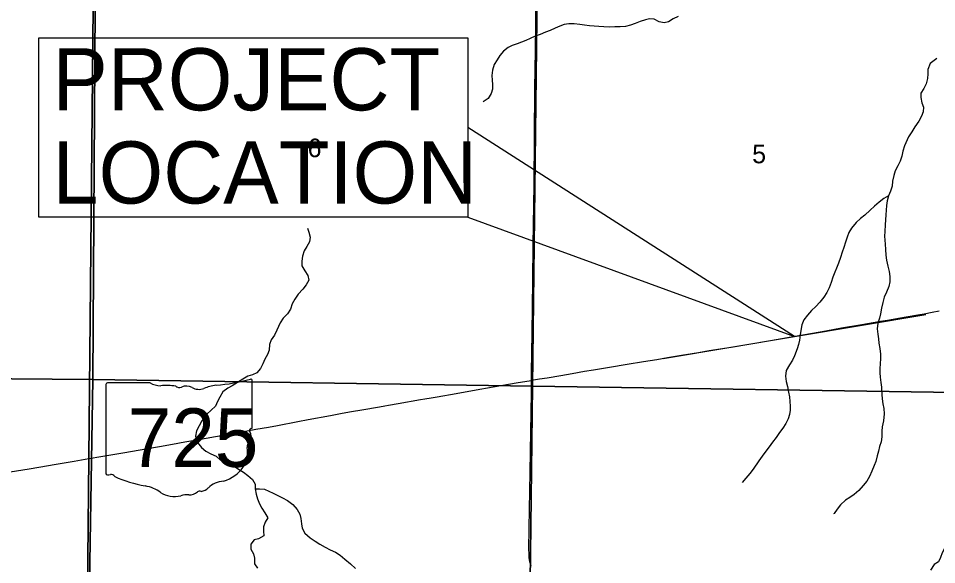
# Model space of a CAD drawing. Extents: x 0 to 34, y 0 to 22.
# Drawn here: x 3.317 to 5.385, y 16.874 to 18.105 of the extents above; entities that cross this region are included whole.
import ezdxf

# ---------------------------------------------------------------- set-up
doc = ezdxf.new("R2010")
doc.units = 0
for name, color, linetype in [('GM_X_Corporation', 7, 'Continuous'), ('GM_X_County_Road', 7, 'Continuous'), ('GM_X_Minor_River', 7, 'Continuous'), ('GM_X_Section_Text', 7, 'Continuous'), ('GM_X_State_Route', 7, 'Continuous'), ('GM_X_State_Shield', 7, 'Continuous'), ('SH_Data', 7, 'Continuous')]:
    doc.layers.add(name, color=color, linetype=linetype)

msp = doc.modelspace()

# ---------------------------------------------------------------- linework, layer by layer
at = {"layer": 'GM_X_Corporation'}
for points in [[(2.4847, 18.3876), (3.4912, 18.3726), (3.4847, 17.2912), (2.4791, 17.2994)], [(3.4912, 18.3726), (4.4615, 18.3587), (4.4872, 18.3578), (4.475, 17.2762), (3.4847, 17.2912)], [(4.4872, 18.3578), (5.4612, 18.3442), (5.4991, 18.3437), (5.4781, 17.2612), (4.475, 17.2762)], [(3.4847, 17.2912), (3.4681, 16.2816), (2.4544, 16.3158), (2.4791, 17.2994)], [(4.475, 17.2762), (4.463, 16.2688), (3.4681, 16.2816), (3.4847, 17.2912)], [(5.4781, 17.2612), (5.4651, 16.258), (4.463, 16.2688), (4.475, 17.2762)]]:
    msp.add_lwpolyline(points, close=True, dxfattribs=at)
for points in [[(3.4672, 16.2781), (3.4754, 17.1134), (3.4875, 18.3666), (3.4876, 18.3718), (3.4864, 18.3719), (3.3947, 18.3734), (3.3557, 18.374), (3.2311, 18.3758)], [(3.4875, 18.3666), (3.4754, 17.1134), (3.4672, 16.2781)]]:
    msp.add_lwpolyline(points, dxfattribs=at)
at = {"layer": 'GM_X_County_Road'}
for points in [[(4.4727, 17.2893), (4.4727, 17.2905), (4.4727, 17.3067), (4.474, 17.3955), (4.4755, 17.5136), (4.4765, 17.5944), (4.4782, 17.7292), (4.4793, 17.8391), (4.4802, 17.9473), (4.4812, 18.0329), (4.482, 18.0907), (4.4827, 18.1677), (4.4833, 18.2397), (4.4839, 18.3062), (4.4838, 18.3193), (4.4834, 18.3262), (4.4827, 18.3312), (4.4817, 18.3355), (4.4807, 18.3391), (4.4789, 18.3438), (4.4765, 18.3487), (4.4749, 18.3519), (4.4733, 18.3544), (4.4712, 18.3572)], [(4.4714, 16.8701), (4.469, 16.8803), (4.4675, 16.89), (4.4669, 16.8986), (4.4667, 16.9079), (4.4675, 16.9557), (4.4692, 17.0825), (4.47, 17.129), (4.4721, 17.2607), (4.4727, 17.2893)]]:
    msp.add_lwpolyline(points, dxfattribs=at)
at = {"layer": 'GM_X_Minor_River'}
for points in [[(4.8026, 18.1094), (4.7915, 18.1043), (4.7811, 18.0973), (4.7712, 18.0949), (4.7603, 18.0973), (4.7486, 18.1036), (4.7384, 18.1038), (4.7289, 18.1017), (4.7174, 18.0978), (4.7056, 18.0934), (4.6956, 18.0898), (4.6842, 18.087), (4.6724, 18.0857), (4.6603, 18.0859), (4.6481, 18.0854), (4.6356, 18.0856), (4.6239, 18.0866), (4.6136, 18.0875), (4.603, 18.0881), (4.592, 18.0895), (4.5814, 18.0912), (4.5682, 18.0929), (4.5568, 18.0924), (4.5462, 18.0911), (4.5362, 18.0875), (4.5259, 18.0827), (4.5148, 18.078), (4.5037, 18.0736), (4.4919, 18.0689), (4.4808, 18.065), (4.4697, 18.0599)], [(4.4697, 18.0599), (4.4594, 18.0551), (4.4498, 18.0515), (4.4399, 18.0479), (4.4292, 18.0439), (4.4196, 18.0392), (4.4096, 18.0314), (4.4011, 18.0213), (4.3948, 18.0116), (4.3885, 18.0011), (4.3849, 17.9886), (4.3832, 17.9762), (4.3837, 17.9655), (4.3847, 17.9556), (4.3849, 17.9458), (4.3813, 17.936), (4.3746, 17.9247), (4.3638, 17.9166)], [(5.3856, 18.0144), (5.3702, 18.0033), (5.365, 17.9898), (5.3648, 17.9799), (5.3643, 17.9697), (5.3614, 17.9576), (5.3563, 17.9467), (5.3492, 17.9362), (5.3494, 17.9267), (5.3519, 17.9149), (5.3551, 17.905), (5.3545, 17.8944), (5.351, 17.8846), (5.3447, 17.873), (5.3361, 17.8606), (5.3287, 17.849), (5.3213, 17.8378), (5.3125, 17.8174), (5.3089, 17.8054), (5.3064, 17.7944), (5.3028, 17.7835), (5.2977, 17.7726), (5.2914, 17.761), (5.2882, 17.7508), (5.2856, 17.7379), (5.2851, 17.727), (5.2807, 17.7157), (5.2763, 17.7047), (5.2734, 17.6934), (5.2721, 17.6832), (5.2712, 17.673), (5.2702, 17.662), (5.2696, 17.651), (5.269, 17.6393), (5.268, 17.6245), (5.2678, 17.6143), (5.269, 17.5961), (5.2695, 17.5839), (5.2704, 17.571), (5.2721, 17.5603), (5.2749, 17.5463), (5.2781, 17.5345), (5.2794, 17.5234), (5.2792, 17.5113), (5.2771, 17.5007), (5.2719, 17.4879), (5.2664, 17.4767), (5.2635, 17.4646), (5.261, 17.4521), (5.2585, 17.4393), (5.2564, 17.4291), (5.2528, 17.4178), (5.2507, 17.4053), (5.2524, 17.3935), (5.2541, 17.3825), (5.255, 17.373), (5.2567, 17.3608), (5.2584, 17.3483), (5.2585, 17.3373), (5.258, 17.3274)], [(5.2763, 17.7047), (5.2663, 17.6992), (5.2552, 17.6911), (5.2451, 17.6818), (5.2355, 17.6729), (5.2235, 17.6617), (5.2135, 17.6536), (5.2039, 17.645), (5.193, 17.6324), (5.1875, 17.6226), (5.1835, 17.6117), (5.1799, 17.6007), (5.1755, 17.5883), (5.1723, 17.5778), (5.1683, 17.5657), (5.1642, 17.5533), (5.1511, 17.5217), (5.1471, 17.5096), (5.1427, 17.4975), (5.1376, 17.4874), (5.1306, 17.4765), (5.1216, 17.4653), (5.1127, 17.4556), (5.1027, 17.4467), (5.0938, 17.4363), (5.086, 17.4254), (5.0812, 17.4141), (5.0791, 17.4017), (5.0778, 17.3914), (5.076, 17.3797), (5.074, 17.3699), (5.0708, 17.3601), (5.0644, 17.3447), (5.06, 17.3345), (5.0534, 17.3237), (5.0463, 17.3113), (5.0442, 17.2984), (5.0459, 17.2863), (5.0491, 17.2752), (5.0515, 17.2623), (5.0536, 17.2516), (5.0545, 17.2413), (5.0551, 17.2311), (5.0553, 17.2216), (5.0536, 17.2118), (5.0508, 17.202), (5.0453, 17.1919), (5.0382, 17.181), (5.0312, 17.1713), (5.0238, 17.16), (5.0153, 17.1496), (5.0075, 17.1391), (5.0001, 17.1294), (4.9919, 17.1185), (4.9841, 17.1077), (4.9713, 17.089), (4.9639, 17.0789), (4.9553, 17.0684), (4.9468, 17.0587)], [(3.9679, 17.6324), (3.9707, 17.6232), (3.9735, 17.6118), (3.9722, 17.6015), (3.9667, 17.591), (3.9604, 17.5809), (3.9564, 17.5692), (3.955, 17.5579), (3.9548, 17.5469), (3.9622, 17.5361), (3.9689, 17.5254), (3.9706, 17.5151), (3.9651, 17.5046), (3.9573, 17.4949), (3.9472, 17.483), (3.939, 17.4721), (3.9335, 17.4616), (3.9295, 17.4495), (3.9225, 17.4394), (3.9128, 17.429), (3.9066, 17.4185), (3.8991, 17.4023), (3.8939, 17.3907), (3.8861, 17.3806), (3.8825, 17.37), (3.8819, 17.3575), (3.8775, 17.347), (3.872, 17.3365), (3.8673, 17.3263), (3.8618, 17.3158), (3.8537, 17.3061), (3.8441, 17.3013), (3.8334, 17.2985)], [(5.258, 17.3274), (5.2566, 17.3153), (5.2568, 17.3058), (5.2578, 17.2959), (5.2591, 17.2842), (5.2604, 17.2739), (5.2616, 17.2572), (5.2622, 17.2477), (5.2635, 17.2363), (5.2656, 17.2257), (5.2669, 17.2139), (5.2655, 17.1976), (5.2625, 17.184), (5.2616, 17.1742), (5.2614, 17.162), (5.2597, 17.1503), (5.256, 17.1398), (5.2536, 17.1292), (5.2507, 17.119), (5.2478, 17.1065), (5.2442, 17.0968), (5.2391, 17.0847), (5.2336, 17.0723), (5.2273, 17.0618), (5.2191, 17.0517), (5.2094, 17.0405), (5.1994, 17.032), (5.1891, 17.0254), (5.1794, 17.0191), (5.1683, 17.0087), (5.1605, 16.999), (5.1539, 16.9892), (5.1523, 16.9881)], [(3.8334, 17.2985), (3.8219, 17.2919), (3.8104, 17.2845), (3.7985, 17.2768), (3.7885, 17.2717), (3.7774, 17.2635), (3.7703, 17.2515), (3.7652, 17.2414), (3.7608, 17.2308), (3.7512, 17.2219), (3.7408, 17.2126), (3.7295, 17.1981), (3.7236, 17.1868), (3.7181, 17.1751), (3.7159, 17.1634), (3.7199, 17.1493), (3.7291, 17.1378), (3.7392, 17.1296), (3.7505, 17.1234), (3.7618, 17.1182), (3.7715, 17.1101), (3.7813, 17.1046), (3.7918, 17.101), (3.8027, 17.0955), (3.8125, 17.0888), (3.8237, 17.0818), (3.8335, 17.0748), (3.8439, 17.0655), (3.8498, 17.0552), (3.85, 17.0445), (3.8524, 17.0328), (3.8556, 17.0221), (3.86, 17.011), (3.8647, 17.0011), (3.8717, 16.9907), (3.8784, 16.9792), (3.8725, 16.9691), (3.8685, 16.9589), (3.8691, 16.949), (3.8693, 16.9388), (3.8578, 16.9322), (3.8475, 16.9297), (3.8401, 16.92), (3.8403, 16.9082), (3.8461, 16.8979), (3.8482, 16.8884), (3.8488, 16.8755), (3.855, 16.8655)], [(3.85, 17.0445), (3.8595, 17.0444), (3.8708, 17.0438), (3.881, 17.0394), (3.8908, 17.0351), (3.9013, 17.0296), (3.9115, 17.0245), (3.9231, 17.0182), (3.9347, 17.0092), (3.9447, 16.9981), (3.9506, 16.9873), (3.9531, 16.9778), (3.9544, 16.966), (3.9557, 16.9561), (3.9616, 16.945), (3.9739, 16.9342), (3.9855, 16.9264), (3.9957, 16.9201), (4.0077, 16.9127), (4.0186, 16.9072), (4.031, 16.9021), (4.0411, 16.8954), (4.0519, 16.8857), (4.065, 16.8753), (4.0758, 16.8648)], [(5.5021, 16.9619), (5.492, 16.9507), (5.4815, 16.9384), (5.4737, 16.9283), (5.4664, 16.9186), (5.4567, 16.9108), (5.4467, 16.9045), (5.4368, 16.9002), (5.424, 16.9068), (5.4131, 16.9139), (5.4028, 16.9099), (5.397, 16.9001), (5.3937, 16.89), (5.389, 16.8802), (5.379, 16.8739), (5.3708, 16.8616)]]:
    msp.add_lwpolyline(points, dxfattribs=at)
at = {"layer": 'GM_X_State_Route'}
for points in [[(3.4766, 17.113), (3.4937, 17.116), (3.5561, 17.1268), (3.6039, 17.1349), (3.6345, 17.1403), (3.6639, 17.1455), (3.6914, 17.1504), (3.7183, 17.1552), (3.7606, 17.1624), (3.8089, 17.1711), (3.8517, 17.1789), (3.8799, 17.1837), (3.9001, 17.1873), (3.9464, 17.1962), (3.9696, 17.2005), (4.0197, 17.2101), (4.0459, 17.2151), (4.0667, 17.2189), (4.0906, 17.223), (4.1304, 17.2297), (4.142, 17.2317), (4.1506, 17.2333), (4.172, 17.2371), (4.2222, 17.2457), (4.232, 17.2474), (4.2461, 17.2498), (4.2602, 17.2522), (4.3024, 17.2598), (4.3562, 17.2693), (4.3905, 17.2753), (4.4382, 17.2837), (4.4714, 17.2891), (4.4727, 17.2893), (4.4904, 17.2922), (4.5075, 17.295), (4.5381, 17.3004), (4.5638, 17.3049), (4.5914, 17.3095), (4.6123, 17.3129), (4.6484, 17.319), (4.6877, 17.3255), (4.7245, 17.3315), (4.7545, 17.3364), (4.7784, 17.3406), (4.8103, 17.3458), (4.8483, 17.352), (4.8728, 17.3562), (4.9219, 17.3639), (4.9617, 17.3704), (5.0107, 17.3789), (5.0364, 17.3833), (5.0572, 17.387), (5.0878, 17.3926), (5.1355, 17.401), (5.1551, 17.4044), (5.1704, 17.4071), (5.2164, 17.4148), (5.2421, 17.4193), (5.2586, 17.4222), (5.2745, 17.425), (5.299, 17.4292), (5.3161, 17.4321), (5.3473, 17.4377), (5.3565, 17.4394), (5.3748, 17.4428), (5.3907, 17.4459)], [(3.2983, 17.0826), (3.3412, 17.0896), (3.3627, 17.0932), (3.4019, 17.1), (3.4423, 17.1069), (3.4757, 17.1128), (3.4766, 17.113)]]:
    msp.add_lwpolyline(points, dxfattribs=at)
at = {"layer": 'GM_X_State_Shield'}
for p, q in [((3.514, 17.28), (3.514, 17.0799)), ((3.6137, 17.2834), (3.5172, 17.2834)), ((3.8436, 17.1837), (3.8436, 17.2884)), ((3.8435, 17.1837), (3.8436, 17.1837))]:
    msp.add_line(p, q, dxfattribs=at)
for centre, major_axis, start_param, end_param in [((3.7262, 17.5563), (0.3495, 0), 4.814394, 5.042369), ((3.8399, 17.2888), (0.00367, 0), 6.141152, 7.989035), ((3.5178, 17.2804), (0.00382, 0), 1.712693, 3.28349), ((3.6367, 17.3067), (0.037, 0), 4.042523, 4.731795), ((3.649, 17.1711), (0.133, 0), 1.404758, 1.657858), ((3.6792, 17.2815), (0.0107, 0), 3.836095, 5.185415), ((3.6949, 17.2583), (0.0222, 0), 0.950623, 2.079405), ((3.7235, 17.2901), (0.0267, 0), 4.081561, 5.145723), ((3.7707, 17.2223), (0.0703, 0), 1.699011, 2.107814), ((3.8427, 17.176), (0.00568, 0), 1.883978, 3.671073), ((3.8066, 17.1628), (0.0341, 0), 5.934695, 6.695948), ((3.8396, 17.1833), (0.00393, 0), 5.05454, 6.418171), ((3.8567, 17.1399), (0.0248, 0), 2.387724, 3.262537), ((3.7457, 17.1266), (0.0874, 0), 5.101752, 6.440018), ((3.5178, 17.0794), (0.00385, 0), 3.00124, 4.508301), ((3.5184, 17.0999), (0.0294, 0), 4.665946, 4.897461), ((3.5244, 17.0683), (0.0106, 0), 0.519207, 1.627899), ((3.6582, 17.2481), (0.2524, 0), 4.195997, 4.488961), ((3.583, 16.99), (0.079, 0), 0.823519, 1.323587), ((3.7219, 17.0605), (0.0282, 0), 4.937069, 5.64225), ((3.7826, 17.0237), (0.0479, 0), 1.647645, 2.488434), ((3.6684, 17.0673), (0.0501, 0), 4.026481, 4.996735), ((3.6973, 16.9981), (0.0412, 0), 1.495662, 1.94098), ((3.701, 17.0524), (0.0267, 0), 4.691044, 5.507374), ((3.7251, 17.033), (0.00752, 0), 1.147584, 2.315152)]:
    msp.add_ellipse(centre, major_axis=major_axis, ratio=0.8, start_param=start_param, end_param=end_param, dxfattribs=at)
at = {"layer": 'SH_Data'}
for p, q in [((5.0645, 17.3882), (5.3604, 17.4376)), ((4.7686, 17.3387), (5.0645, 17.3882))]:
    msp.add_line(p, q, dxfattribs=at)
for points in [[(3.363, 18.0609), (4.329, 18.0609), (4.329, 17.6566), (3.363, 17.6566)], [(4.329, 17.6566), (5.0645, 17.3882), (4.329, 17.8588)]]:
    msp.add_lwpolyline(points, close=True, dxfattribs=at)

# ---------------------------------------------------------------- texts
at = {"layer": 'GM_X_Section_Text'}
for s, p in [('6', (3.9682, 17.7921)), ('5', (4.9695, 17.7784))]:
    msp.add_text(s, height=0.0419, rotation=0, dxfattribs=at).set_placement(p)
at = {"layer": 'GM_X_State_Shield'}
msp.add_text('725', height=0.13184, dxfattribs=at).set_placement((3.5631, 17.094))
at = {"layer": 'SH_Data'}
for s, p in [('PROJECT ', (3.3932, 17.8977)), ('LOCATION', (3.3932, 17.6877))]:
    msp.add_text(s, height=0.14, dxfattribs=at).set_placement(p)

doc.saveas('drawing.dxf')
